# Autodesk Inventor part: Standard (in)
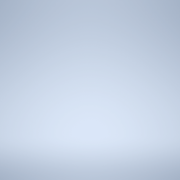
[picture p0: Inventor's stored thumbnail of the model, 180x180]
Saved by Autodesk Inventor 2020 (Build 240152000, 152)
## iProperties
Created: 2019-02
Part Number: Standard (in)
Material: Ogólny
Document SubType Name: Modeling
Density: 1 g/cm^3
Appearance: Domyślna
Catalog Web Link: www.expertbooks.pl
Designer: F.Stasiak
Manager: www.cadconsulting.pl
Company: Fabian Stasiak CAD Consulting
Subject: Zbiór ćwiczeń. Autodesk Inventor 2020. Kurs Professional
Author: F.Stasiak
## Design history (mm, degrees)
